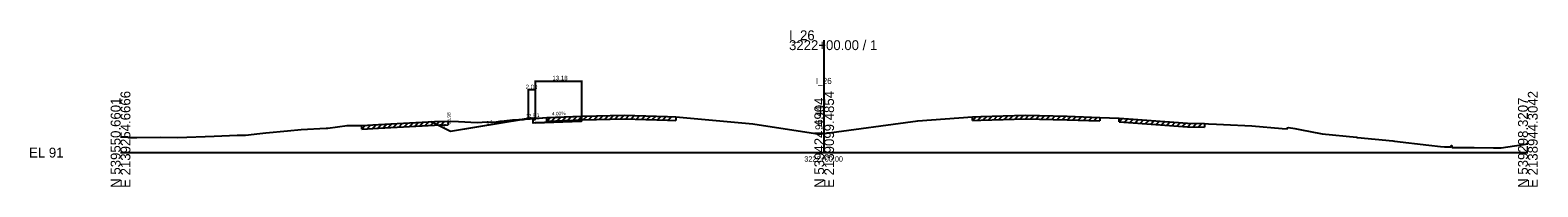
# Model space of a CAD drawing. Extents: x -13101 to 4803, y -924 to 22390.
# Drawn here: x 1974.3 to 2402.8, y 10990.3 to 11034.7 of the extents above; entities that cross this region are included whole.
import ezdxf

# ---------------------------------------------------------------- set-up
doc = ezdxf.new("R2010")
doc.units = 0
for name, color, linetype in [('RD_GPK_XS_Cell', 7, 'Continuous'), ('RD_XD_TX_Width', 7, 'Continuous'), ('RD_XS_Base', 7, 'Continuous'), ('RD_XS_EarthShd', 7, 'Continuous'), ('RD_XS_EwShp', 7, 'Continuous'), ('RD_XS_ExGround', 7, 'Continuous'), ('RD_XS_ExPaveRet', 7, 'Continuous'), ('RD_XS_OSBase', 7, 'Continuous'), ('RD_XS_Pave', 7, 'Continuous'), ('RD_XS_TieSlope', 7, 'Continuous'), ('RD_XS_TX_Baseline', 7, 'Continuous'), ('RD_XS_TX_Elev_EX', 7, 'Continuous'), ('RD_XS_TX_Elev_PR', 7, 'Continuous'), ('RD_XS_TX_ShdSlope', 7, 'Continuous'), ('RD_XS_TX_Slope', 7, 'Continuous'), ('RD_XS_TX_Station', 7, 'Continuous')]:
    doc.layers.add(name, color=color, linetype=linetype)

msp = doc.modelspace()

# ---------------------------------------------------------------- linework, layer by layer
at = {"layer": 'RD_GPK_XS_Cell'}
for p, q in [((2200, 11000), (2200, 11031.87)), ((2000, 11000), (2200, 11000)), ((2200, 11000), (2400, 11000))]:
    msp.add_line(p, q, dxfattribs=at)
at = {"layer": 'RD_XD_TX_Width'}
for p, q in [((2115.82, 11017.96), (2115.82, 11009.85)), ((2117.82, 11017.76), (2115.82, 11017.76)), ((2117.82, 11020.48), (2117.82, 11010.01)), ((2117.82, 11020.28), (2131, 11020.28)), ((2117.82, 11017.96), (2117.82, 11010.01)), ((2131, 11020.48), (2131, 11010.53))]:
    msp.add_line(p, q, dxfattribs=at)
at = {"layer": 'RD_XS_Base'}
msp.add_line((2117.82, 11008.41), (2131, 11008.93), dxfattribs=at)
at = {"layer": 'RD_XS_EarthShd'}
msp.add_line((2117.82, 11009.81), (2115.82, 11009.65), dxfattribs=at)
at = {"layer": 'RD_XS_EwShp'}
for points in [[(2093.82, 11005.98), (2088.3, 11008.74), (2089.27, 11008.79), (2093.11, 11008.92), (2096.05, 11008.81), (2101.35, 11008.52), (2102.74, 11008.67), (2106.88, 11008.72), (2107.87, 11008.9), (2109.07, 11008.99), (2111.36, 11009.26), (2114.51, 11009.43)], [(2115.03, 11009.45), (2117.82, 11009.66), (2117.82, 11009.81), (2115.82, 11009.65), (2114.51, 11009.43)], [(2117.32, 11009.39), (2117.82, 11009.41), (2117.82, 11009.66), (2121.13, 11009.91), (2131, 11010.33), (2131, 11009.93), (2131, 11008.93), (2117.82, 11008.41), (2117.32, 11008.39)]]:
    msp.add_lwpolyline(points, close=True, dxfattribs=at)
at = {"layer": 'RD_XS_ExGround'}
msp.add_lwpolyline([(2000, 11004.48), (2001.97, 11004.51), (2002.34, 11004.32), (2004.65, 11004.31), (2011.26, 11004.42), (2016.28, 11004.29), (2026.63, 11004.7), (2033.14, 11004.98), (2035.54, 11004.92), (2039.59, 11005.38), (2041.29, 11005.58), (2047.42, 11006.18), (2051.3, 11006.58), (2058.46, 11006.91), (2058.94, 11006.94), (2064.4, 11007.68), (2067.17, 11007.71), (2068.6, 11007.68), (2073.33, 11007.96), (2089.27, 11008.79), (2093.11, 11008.92), (2096.05, 11008.81), (2101.35, 11008.52), (2102.74, 11008.67), (2106.88, 11008.72), (2107.87, 11008.9), (2109.07, 11008.99), (2111.36, 11009.26), (2115.03, 11009.45), (2121.13, 11009.91), (2131.27, 11010.34), (2143.11, 11010.62), (2155.49, 11010.22), (2157.84, 11010.11), (2179.73, 11008.13), (2198.74, 11005.27), (2200, 11005.44), (2226.58, 11008.99), (2242.17, 11010.14), (2244.55, 11010.23), (2257.22, 11010.59), (2269.02, 11010.3), (2278.39, 11009.98), (2283.87, 11009.72), (2287.79, 11009.48), (2303.29, 11008.35), (2308.09, 11008.22), (2309.24, 11008.16), (2311.55, 11008.07), (2313.54, 11007.95), (2321.56, 11007.55), (2330.13, 11006.86), (2331.57, 11006.75), (2331.68, 11007.02), (2331.97, 11007.16), (2333.78, 11006.84), (2335.2, 11006.54), (2341.58, 11005.29), (2351.25, 11004.34), (2351.59, 11004.31), (2361.62, 11003.34), (2362.13, 11003.27), (2371.87, 11002.08), (2375.21, 11001.73), (2376.28, 11001.67), (2378.15, 11001.62), (2378.32, 11001.97), (2378.47, 11001.49), (2380.03, 11001.47), (2383.01, 11001.46), (2384.75, 11001.45), (2390.2, 11001.39), (2391.85, 11001.37), (2392.4, 11001.36), (2400, 11002.47)], dxfattribs=at)
at = {"layer": 'RD_XS_ExPaveRet'}
for p, q in [((2121.13, 11008.91), (2122.17, 11009.95)), ((2121.13, 11008.91), (2121.13, 11009.91)), ((2121.13, 11008.91), (2131.27, 11009.34)), ((2122.63, 11008.97), (2123.67, 11010.02)), ((2124.13, 11009.04), (2125.17, 11010.08)), ((2125.63, 11009.1), (2126.67, 11010.15)), ((2127.13, 11009.17), (2128.17, 11010.21)), ((2128.63, 11009.23), (2129.67, 11010.28)), ((2130.13, 11009.3), (2131.17, 11010.34)), ((2131.27, 11009.34), (2143.11, 11009.62)), ((2131.63, 11009.35), (2132.65, 11010.38)), ((2133.13, 11009.39), (2134.15, 11010.41)), ((2134.63, 11009.42), (2135.65, 11010.45)), ((2136.13, 11009.46), (2137.15, 11010.48)), ((2137.63, 11009.49), (2138.65, 11010.52)), ((2139.13, 11009.53), (2140.15, 11010.55)), ((2140.63, 11009.56), (2141.65, 11010.59)), ((2142.13, 11009.6), (2143.15, 11010.62)), ((2143.11, 11009.62), (2155.49, 11009.22)), ((2143.63, 11009.61), (2144.6, 11010.57)), ((2145.13, 11009.56), (2146.1, 11010.52)), ((2146.63, 11009.51), (2147.6, 11010.48)), ((2148.13, 11009.46), (2149.1, 11010.43)), ((2149.63, 11009.41), (2150.6, 11010.38)), ((2151.13, 11009.36), (2152.1, 11010.33)), ((2152.63, 11009.31), (2153.6, 11010.28)), ((2154.13, 11009.26), (2155.1, 11010.23)), ((2155.49, 11009.22), (2157.84, 11009.11)), ((2155.63, 11009.21), (2156.59, 11010.17)), ((2157.84, 11010.11), (2157.84, 11009.11)), ((2242.17, 11009.14), (2243.21, 11010.18)), ((2242.17, 11009.14), (2242.17, 11010.14)), ((2242.17, 11009.14), (2244.55, 11009.23)), ((2243.67, 11009.19), (2244.71, 11010.23)), ((2244.55, 11009.23), (2257.22, 11009.59)), ((2245.17, 11009.25), (2246.2, 11010.28)), ((2246.67, 11009.29), (2247.7, 11010.32)), ((2248.17, 11009.33), (2249.2, 11010.36)), ((2249.67, 11009.38), (2250.7, 11010.41)), ((2251.17, 11009.42), (2252.2, 11010.45)), ((2252.67, 11009.46), (2253.7, 11010.49)), ((2254.17, 11009.51), (2255.2, 11010.54)), ((2255.67, 11009.55), (2256.7, 11010.58)), ((2257.17, 11009.59), (2258.15, 11010.57)), ((2257.22, 11009.59), (2269.02, 11009.3)), ((2258.67, 11009.56), (2259.65, 11010.53)), ((2260.17, 11009.52), (2261.15, 11010.5)), ((2261.67, 11009.48), (2262.65, 11010.46)), ((2263.17, 11009.45), (2264.15, 11010.42)), ((2264.67, 11009.41), (2265.65, 11010.39)), ((2266.17, 11009.37), (2267.15, 11010.35)), ((2267.67, 11009.34), (2268.65, 11010.31)), ((2269.02, 11009.3), (2278.39, 11008.98)), ((2269.17, 11009.3), (2270.14, 11010.26)), ((2270.67, 11009.25), (2271.64, 11010.21)), ((2272.17, 11009.19), (2273.14, 11010.16)), ((2273.67, 11009.14), (2274.64, 11010.11)), ((2275.17, 11009.09), (2276.14, 11010.06)), ((2276.67, 11009.04), (2277.64, 11010.01)), ((2278.39, 11009.98), (2278.39, 11008.98)), ((2283.87, 11008.72), (2283.87, 11009.72)), ((2283.87, 11008.72), (2284.81, 11009.66)), ((2285.37, 11008.63), (2286.31, 11009.57)), ((2286.87, 11008.54), (2287.81, 11009.48)), ((2288.37, 11008.44), (2289.3, 11009.37)), ((2289.87, 11008.33), (2290.8, 11009.26)), ((2291.37, 11008.22), (2292.3, 11009.15)), ((2292.87, 11008.11), (2293.8, 11009.04)), ((2068.6, 11006.68), (2069.66, 11007.74)), ((2068.6, 11006.68), (2068.6, 11007.68)), ((2068.6, 11006.68), (2073.33, 11006.96)), ((2070.1, 11006.77), (2071.16, 11007.83)), ((2071.6, 11006.86), (2072.66, 11007.92)), ((2073.1, 11006.94), (2074.16, 11008)), ((2073.33, 11006.96), (2089.27, 11007.79)), ((2074.6, 11007.02), (2075.65, 11008.08)), ((2076.1, 11007.1), (2077.15, 11008.16)), ((2077.6, 11007.18), (2078.65, 11008.23)), ((2079.1, 11007.26), (2080.15, 11008.31)), ((2080.6, 11007.34), (2081.65, 11008.39)), ((2082.1, 11007.41), (2083.15, 11008.47)), ((2083.6, 11007.49), (2084.65, 11008.55)), ((2085.1, 11007.57), (2086.15, 11008.63)), ((2086.6, 11007.65), (2087.65, 11008.7)), ((2088.1, 11007.73), (2089.15, 11008.78)), ((2089.27, 11007.79), (2093.11, 11007.92)), ((2089.6, 11007.8), (2090.64, 11008.84)), ((2091.1, 11007.85), (2092.14, 11008.89)), ((2093.11, 11008.92), (2093.11, 11007.92)), ((2283.87, 11008.72), (2287.79, 11008.48)), ((2287.79, 11008.48), (2303.29, 11007.35)), ((2294.37, 11008), (2295.3, 11008.93)), ((2295.87, 11007.89), (2296.8, 11008.82)), ((2297.37, 11007.78), (2298.3, 11008.71)), ((2298.87, 11007.67), (2299.8, 11008.6)), ((2300.37, 11007.56), (2301.3, 11008.49)), ((2301.87, 11007.45), (2302.8, 11008.38)), ((2303.29, 11007.35), (2308.09, 11007.22)), ((2303.37, 11007.35), (2304.34, 11008.32)), ((2304.87, 11007.31), (2305.84, 11008.28)), ((2306.37, 11007.27), (2307.34, 11008.24)), ((2308.09, 11008.22), (2308.09, 11007.22))]:
    msp.add_line(p, q, dxfattribs=at)
at = {"layer": 'RD_XS_OSBase'}
for p, q in [((2117.32, 11009.39), (2117.82, 11009.41)), ((2117.32, 11008.39), (2117.32, 11009.39)), ((2117.82, 11009.41), (2117.82, 11009.81)), ((2131, 11009.93), (2131, 11010.33)), ((2131, 11008.93), (2131, 11009.93)), ((2117.82, 11008.41), (2117.32, 11008.39))]:
    msp.add_line(p, q, dxfattribs=at)
at = {"layer": 'RD_XS_Pave'}
msp.add_line((2117.82, 11009.81), (2131, 11010.33), dxfattribs=at)
at = {"layer": 'RD_XS_TieSlope'}
for p, q in [((2115.82, 11009.65), (2093.82, 11005.98)), ((2093.82, 11005.98), (2088.3, 11008.74))]:
    msp.add_line(p, q, dxfattribs=at)

# ---------------------------------------------------------------- texts
at = {"layer": 'RD_GPK_XS_Cell'}
for s, p in [('3222+00.00 / 1', (2190, 11029.07)), ('I_26', (2190, 11031.87)), ('EL 91', (1974, 10998.6))]:
    msp.add_text(s, height=2.8, dxfattribs=at).set_placement(p)
for s, p in [('N 539550.6601', (2000, 10990)), ('E 2139254.6666', (2002.8, 10990)), ('N 539424.4904', (2200, 10990)), ('E 2139099.4854', (2202.8, 10990)), ('N 539298.3207', (2400, 10990)), ('E 2138944.3042', (2402.8, 10990))]:
    msp.add_text(s, height=2.8, rotation=90, dxfattribs=at).set_placement(p)
at = {"layer": 'RD_XD_TX_Width'}
for s, p in [('2.00', (2115.13, 11018.01)), ('13.18', (2122.75, 11020.53))]:
    msp.add_text(s, height=1.25, dxfattribs=at).set_placement(p)
at = {"layer": 'RD_XS_TX_Baseline'}
msp.add_text('I_26', height=1.75, dxfattribs=at).set_placement((2197.6, 11019.44))
at = {"layer": 'RD_XS_TX_Elev_EX'}
msp.add_text('96.44', height=2, rotation=90, dxfattribs=at).set_placement((2199.5, 11006.44))
at = {"layer": 'RD_XS_TX_Elev_PR'}
msp.add_text('96.98', height=1, rotation=90, dxfattribs=at).set_placement((2093.82, 11007.98))
at = {"layer": 'RD_XS_TX_ShdSlope'}
msp.add_text('12.5:1', height=1, rotation=4.5739, dxfattribs=at).set_placement((2115.29, 11009.85))
msp.add_text('12.5:1', height=1, rotation=4.5739, dxfattribs=at).set_placement((2115.29, 11009.85))
at = {"layer": 'RD_XS_TX_Slope'}
for s, rotation, p in [('6:1', 9.4623, (2104.08, 11007.94)), ('4.00%', 2.2906, (2122.59, 11010.5)), ('2:1', 333.4349, (2090.5, 11007.92))]:
    msp.add_text(s, height=1, rotation=rotation, dxfattribs=at).set_placement(p)
at = {"layer": 'RD_XS_TX_Station'}
msp.add_text('3222+00.00', height=1.5, dxfattribs=at).set_placement((2194.34, 10997.44))

doc.saveas('drawing.dxf')
